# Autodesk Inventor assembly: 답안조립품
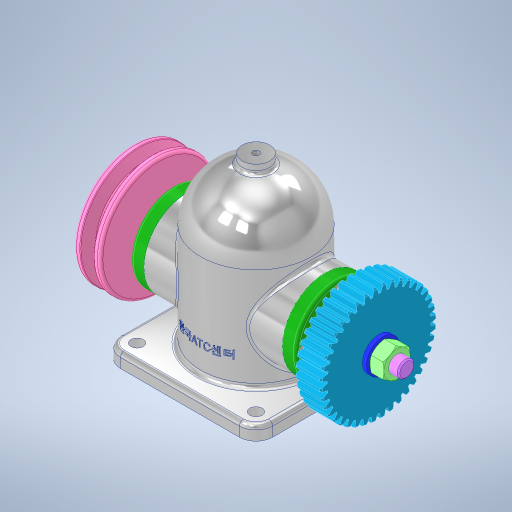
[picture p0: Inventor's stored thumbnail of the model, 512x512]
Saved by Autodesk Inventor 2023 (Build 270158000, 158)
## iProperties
Created: 2025-04
Part Number: 답안조립품
Document SubType Name: Assembly
Designer: User
Author: User
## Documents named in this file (13)
- C:\Users\User\Desktop\750406V1018\답안조립품.iam
- C:\Users\User\Desktop\750406V1018\본체.ipt
- C:\Users\User\Desktop\750406V1018\깊은 홈 볼 베어링 6203.ipt
- C:\Users\User\Desktop\750406V1018\축.ipt
- C:\Users\User\Desktop\750406V1018\커버.ipt
- C:\Users\User\Desktop\750406V1018\오일 실 26 38 8.ipt
- C:\Users\User\Desktop\750406V1018\6각 구멍붙이 볼트 M4x12.ipt
- C:\Users\User\Desktop\750406V1018\칼라.ipt
- C:\Users\User\Desktop\750406V1018\평행 키 5x5x12.ipt
- C:\Users\User\Desktop\750406V1018\스퍼기어.ipt
- C:\Users\User\Desktop\750406V1018\V 벨트 풀리.ipt
- C:\Users\User\Desktop\750406V1018\평와셔 M12.ipt
- C:\Users\User\Desktop\750406V1018\6각 너트 M12x1.ipt
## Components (11 placed, 3 different names)
1. 6각 구멍붙이 볼트 M4x12:1
2. 6각 구멍붙이 볼트 M4x12:2
3. 6각 구멍붙이 볼트 M4x12:3
4. 6각 구멍붙이 볼트 M4x12:4
5. 6각 구멍붙이 볼트 M4x12:5
6. 6각 구멍붙이 볼트 M4x12:6
7. 6각 구멍붙이 볼트 M4x12:7
8. 6각 구멍붙이 볼트 M4x12:8
9. V 벨트 풀리:1
10. 6각 너트 M12x1:1
11. 6각 너트 M12x1:2
